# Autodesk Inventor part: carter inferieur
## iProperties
Author: Administrateur
Shininess: 54.0
PropertySet Name: _Private Model Information
Length Units: 11269
Angle Units: 11283
Time Units: 11279
Mass Units: 11290
Length Display Precision: 3
Angle Display Precision: 2
Compacted: False
Created: 2001-04
Part Number: carter inferieur
Material: Par défaut
Document SubType Name: Modélisation
Designer: Administrateur
Control State: 0
Master: False
Checked Out: False
PropertySet Name: Design Tracking Control
Density: 0.0
Volumn: 0.0
Area: 0.0
PropertySet Name: Model Information
